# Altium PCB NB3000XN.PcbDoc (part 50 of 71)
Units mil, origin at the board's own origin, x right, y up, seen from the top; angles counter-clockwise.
Board outline 9527.56 x 6929.77 mil, 6 copper layers (Top Layer, GND+SHIELD, MidLayer1, MidLayer2, P2 - 3V3+5V0, Bottom Layer), stack 62.375 mil thick; 832 components, 1027 nets, 4655 pads, 4981 vias.
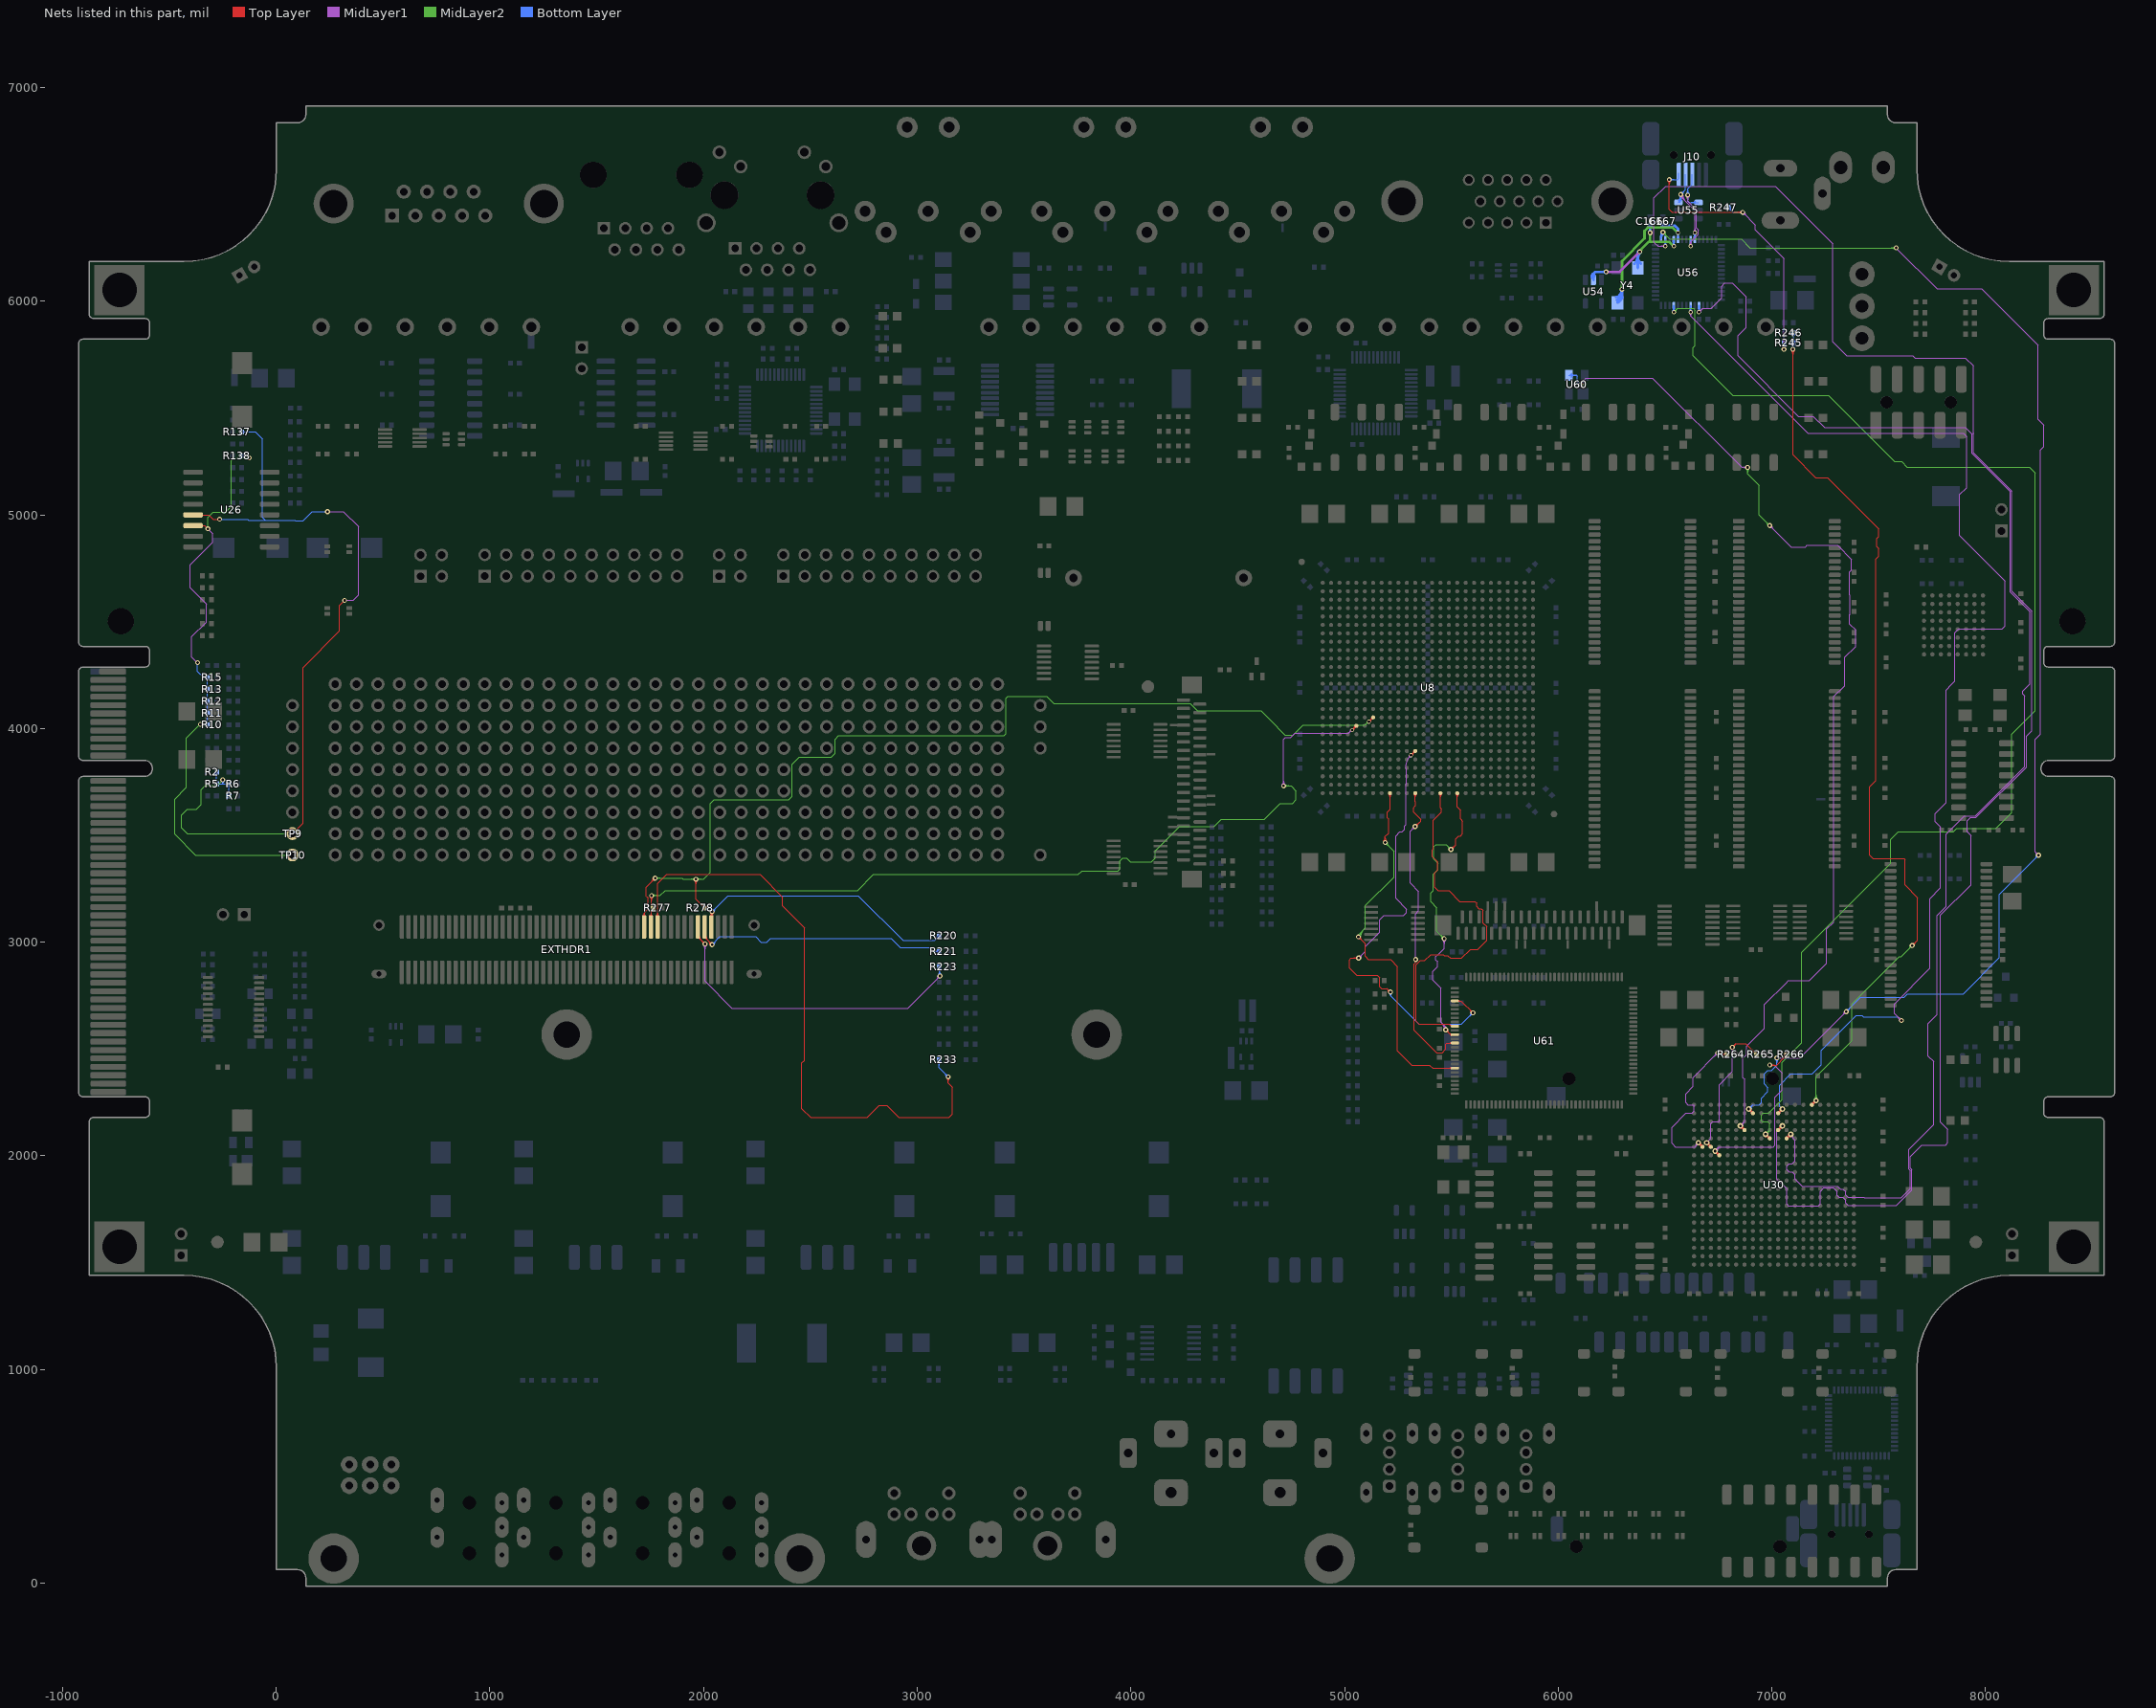
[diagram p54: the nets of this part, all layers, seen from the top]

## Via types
v1: diameter 23, hole 11.81, Top Layer to Bottom Layer, 3672 vias
v2: diameter 26, hole 11.81, Top Layer to Bottom Layer, 461 vias
v3: diameter 19, hole 11.81, Top Layer to Bottom Layer, tented both sides, 396 vias
v4: diameter 23.62, hole 11.81, Top Layer to Bottom Layer, 288 vias
v5: diameter 20, hole 11.81, Top Layer to Bottom Layer, 91 vias
v6: diameter 23, hole 11.81, Top Layer to Bottom Layer, tented both sides, 50 vias
v7: diameter 31, hole 11.81, Top Layer to Bottom Layer, 15 vias
v8: diameter 27.56, hole 11.81, Top Layer to Bottom Layer, tented both sides, 4 vias
v9: diameter 29, hole 11.81, Top Layer to Bottom Layer, 3 vias
v10: diameter 21, hole 11.81, Top Layer to Bottom Layer, 1 vias

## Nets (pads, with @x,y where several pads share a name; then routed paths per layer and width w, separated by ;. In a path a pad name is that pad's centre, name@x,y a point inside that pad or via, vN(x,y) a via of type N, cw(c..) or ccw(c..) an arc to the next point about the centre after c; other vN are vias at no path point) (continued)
HOST_USB.PKTEND: U30.L5 U56.39 | length 6330.3
  Top Layer w8: v2@6970.63,2092.22 cw(c6970.63,2070.49) 6985.99,2085.86 cw(c7001.36,2101.22) v2@6979.63,2101.22 ; v2(6970.63,2101.22) U30.L5@6990.31,2081.54 ; U30.L5@6984.47,2081.54 ccw(c6970.37,2081.54) 6980.34,2091.51 ccw(c6990.31,2101.48) U30.L5@6990.31,2087.38
  MidLayer2 w4: v5(6541.1,5949.34) 6557.66,5965.9 6632.66,5965.9 6640.19,5958.37 6640.19,5792.37 6631.86,5784.04 6631.86,5744.69 6818.17,5558.37 7265.19,5558.37 7573.52,5250.04 7606.86,5250.04 7632.9,5224 8204.69,5224 8231.86,5196.83 8231.86,4082.75 8122.86,3973.75 8122.86,3607.71 8048.52,3533.37 7865.19,3533.37 7848.52,3516.71 7591.86,3516.71 7556.86,3481.71 7556.86,3369.08 7139.86,2952.08 7139.86,2530.06 7048.52,2438.73 7048.52,2263.71 6984.86,2200.04 6959.19,2200.04 6950.86,2191.71 6950.86,2161.71 6952.86,2159.71 6981.86,2159.71 6990.19,2151.37 6990.19,2120.78 v2(6970.63,2101.22) ; v5@6541.1,5957.34 ccw(c6541.1,5976.65) 6554.76,5963 ccw(c6568.42,5949.34) v5@6549.1,5949.34 ; v2@6970.63,2108.22 ccw(c6970.63,2125.12) 6982.58,2113.17 ccw(c6994.53,2101.22) v2@6977.63,2101.22 ; v2@6970.63,2112.22 ccw(c6970.63,2138.78) 6989.41,2120 ccw(c7008.18,2101.22) v2@6981.63,2101.22
  Bottom Layer w8: v5@6536.86,5953.58 ccw(c6526.62,5963.82) 6541.1,5963.82 ccw(c6555.59,5963.82) v5@6545.34,5953.58 ; v5(6541.1,5949.34) U56.39@6541.1,5980.67
HOST_USB.RD_N: U30.N2 U56.1 | length 7277.6
  Top Layer w8: v2@6891.89,2210.33 cw(c6891.89,2188.6) 6907.25,2203.97 cw(c6922.62,2219.33) v2@6900.89,2219.33 ; v2(6891.89,2219.33) U30.N2@6911.57,2199.65 ; U30.N2@6905.73,2199.65 ccw(c6891.63,2199.65) 6901.6,2209.62 ccw(c6911.57,2219.59) U30.N2@6911.57,2205.49
  MidLayer1 w4: v1(7023.52,2458.37) 7131.86,2458.37 v1(7348.52,2675.04) ; v1@7027.41,2454.49 cw(c7036.8,2445.1) 7036.8,2458.37 cw(c7036.8,2471.65) v1@7027.41,2462.26 ; v1@7030.24,2451.66 cw(c7046.46,2435.44) 7046.46,2458.37 cw(c7046.46,2481.31) v1@7030.24,2465.09 ; v1@7339.02,2675.04 cw(c7316.09,2675.04) 7332.31,2658.82 cw(c7348.52,2642.61) v1@7348.52,2665.54 ; v1@7343.02,2675.04 cw(c7329.75,2675.04) 7339.14,2665.65 cw(c7348.52,2656.26) v1@7348.52,2669.54 ; v1(7581.86,6250.04) 7773.52,6058.37 7981.63,6058.37 8245,5795 8245,5448.52 8273.52,5420 8273.52,5320 8256.86,5303.33 8256.86,3974.43 8231.52,3949.1 8231.52,3424.04 v1(8248.52,3407.04) ; v1@8239.02,3407.04 ccw(c8216.09,3407.04) 8232.31,3423.26 ccw(c8248.52,3439.48) v1@8248.52,3416.54 ; v1@8243.02,3407.04 ccw(c8229.75,3407.04) 8239.14,3416.43 ccw(c8248.52,3425.82) v1@8248.52,3412.54
  MidLayer2 w4: v1@6490.19,6313.87 cw(c6490.19,6290.94) 6506.41,6307.16 cw(c6522.63,6323.37) v1@6499.69,6323.37 ; v1@6490.19,6317.87 cw(c6490.19,6304.6) 6499.58,6313.99 cw(c6508.97,6323.37) v1@6495.69,6323.37 ; v1(6490.19,6323.37) 6521.86,6291.71 6856.86,6291.71 6898.52,6250.04 v1(7581.86,6250.04) ; v1@7575.14,6243.32 ccw(c7558.92,6227.11) 7558.92,6250.04 ccw(c7558.92,6272.98) v1@7575.14,6256.76 ; v1@7577.97,6246.15 ccw(c7568.58,6236.76) 7568.58,6250.04 ccw(c7568.58,6263.32) v1@7577.97,6253.93
  Bottom Layer w4: U56.1@6479.22,6303.09 ccw(c6472.39,6309.92) 6482.05,6309.92 ccw(c6491.7,6309.92) U56.1@6484.88,6303.09 ; U56.1@6482.05,6288.37 cw(c6516.09,6288.37) v1@6495.84,6315.74 ; U56.1@6482.05,6289.33 6482.05,6315.23 v1(6490.19,6323.37) ; U56.1@6482.05,6296.31 cw(c6510.22,6296.31) v1@6493.46,6318.95 ; U56.1@6482.05,6304.24 cw(c6504.35,6304.24) v1@6491.08,6322.17 ; 6482.05,6312.18 cw(c6498.47,6312.18) v1@6488.7,6325.38 ; v2(6891.89,2219.33) 6910.93,2238.37 6940.19,2238.37 6951.52,2249.71 6951.52,2269.71 6981.86,2300.04 6981.86,2320.04 6965.19,2336.71 6965.19,2383.37 6981.86,2400.04 6998.52,2400.04 7023.52,2425.04 v1(7023.52,2458.37) ; v2@6891.89,2226.33 ccw(c6891.89,2243.23) 6903.84,2231.28 ccw(c6915.79,2219.33) v2@6898.89,2219.33 ; v2@6891.89,2230.33 ccw(c6891.89,2256.89) 6910.67,2238.11 ccw(c6929.45,2219.33) v2@6902.89,2219.33 ; v1@7016.81,2451.66 cw(c7000.59,2435.44) 7023.52,2435.44 cw(c7046.46,2435.44) v1@7030.24,2451.66 ; v1@7019.64,2454.49 cw(c7010.25,2445.1) 7023.52,2445.1 cw(c7036.8,2445.1) v1@7027.41,2454.49 ; v1(7348.52,2675.04) 7415.19,2741.71 7618.17,2741.71 7635.17,2758.71 7895.88,2758.71 8065.19,2928.02 8065.19,3223.71 v1(8248.52,3407.04) ; v1@7348.52,2680.54 ccw(c7348.52,2693.82) 7357.91,2684.43 ccw(c7367.3,2675.04) v1@7354.02,2675.04 ; v1@7348.52,2684.54 ccw(c7348.52,2707.48) 7364.74,2691.26 ccw(c7380.96,2675.04) v1@7358.02,2675.04 ; v1@8239.02,3407.04 cw(c8216.09,3407.04) 8232.31,3390.82 cw(c8248.52,3374.61) v1@8248.52,3397.54 ; v1@8243.02,3407.04 cw(c8229.75,3407.04) 8239.14,3397.65 cw(c8248.52,3388.26) v1@8248.52,3401.54
HOST_USB.READY: U30.J5 U56.33 | length 6901
  Top Layer w8: U30.J5@7069.06,2081.54 v2(7088.74,2101.22) ; U30.J5@7069.06,2087.38 ccw(c7069.06,2101.48) 7079.03,2091.51 ccw(c7089,2081.54) U30.J5@7074.9,2081.54 ; v2@7079.74,2101.22 cw(c7058.01,2101.22) 7073.38,2085.86 cw(c7088.74,2070.49) v2@7088.74,2092.22
  MidLayer1 w4: v5(6659.21,5949.34) 6676.58,5966.71 6715.86,5966.71 6765.19,6016.04 6765.19,6070 6780.19,6085 6815,6085 6880,6020 6880,5877.69 6841,5838.69 6841,5744.49 7125.14,5460.35 7194.18,5460.35 7246.15,5408.37 7905.23,5408.37 7934.28,5379.32 7936,5377.6 7936,5287.56 8115.19,5108.37 8115.19,4640 8208.52,4546.67 8208.52,4208.73 8175,4175.2 8175,4162.13 8183.19,4153.94 8183.19,3822.13 8150.03,3788.97 7952.43,3591.37 7901.17,3591.37 7815.19,3505.39 7815.19,3166.71 7773.52,3125.04 7773.52,2661.08 7731.52,2619.08 7731.52,2467.04 7756.86,2441.71 7756.86,2145.71 7640.52,2029.37 7640.52,1939.22 7647.5,1932.25 7647.5,1846 7605,1803.5 7535,1803.5 7432.63,1803.5 7430,1806.13 7356.96,1806.13 7345.33,1817.76 7345.33,1832.13 7332.83,1844.63 7320.6,1844.63 7315.19,1850.04 7306.86,1858.37 7141.19,1858.37 7108.36,1891.21 7108.36,1911.62 7095.24,1924.74 7080.87,1924.74 7069.74,1935.87 7069.74,1951.61 7080.87,1962.74 7095.24,1962.74 7108.36,1975.86 7108.36,2072.27 7099.02,2081.6 7098.92,2081.6 7098.92,2091.04 v2(7088.74,2101.22) ; v5@6659.21,5957.34 ccw(c6659.21,5976.66) 6672.87,5963 ccw(c6686.52,5949.34) v5@6667.21,5949.34 ; v2@7088.44,2094.23 cw(c7087.98,2083.29) 7098.92,2083.29 ; v2@7088.61,2098.22 cw(c7088.15,2087.47) 7098.92,2087.47 ; v2@7088.78,2102.22 cw(c7088.33,2091.64) 7098.92,2091.64
  Bottom Layer w8: v5@6654.97,5953.58 ccw(c6644.73,5963.82) 6659.21,5963.82 ccw(c6673.7,5963.82) v5@6663.45,5953.58 ; v5(6659.21,5949.34) U56.33@6659.21,5980.67
HOST_USB.RESET_N: U30.P4 U60.3 | length 5349.1
  Top Layer w8: v2@6852.52,2131.59 cw(c6852.52,2109.86) 6867.88,2125.23 cw(c6883.25,2140.59) v2@6861.52,2140.59 ; v2(6852.52,2140.59) U30.P4@6872.2,2120.91 ; U30.P4@6866.36,2120.91 ccw(c6852.26,2120.91) 6862.23,2130.88 ccw(c6872.2,2140.85) U30.P4@6872.2,2126.75
  MidLayer1 w4: v1@6104.86,5620.21 ccw(c6104.86,5633.49) 6114.25,5624.1 ccw(c6123.64,5614.71) v1@6110.36,5614.71 ; 6104.86,5624.21 ccw(c6104.86,5647.14) 6121.07,5630.93 ccw(c6137.29,5614.71) v1@6114.36,5614.71 ; v1(6105,5610) 6105,5614.56 6104.86,5614.71 6130.15,5640 6441.29,5640 6858.92,5222.37 v1(6886.86,5222.37) ; v2(6852.52,2140.59) 6852.52,2141.71 6872.86,2162.04 6872.86,2358.37 6865.19,2366.04 6865.19,2457.37 6881.86,2474.04 6881.86,2514.34 6965.19,2597.67 6965.19,2708.37 7069.5,2812.68 7076.82,2820 7176.21,2820 7256.86,2900.65 7256.86,3061.35 7290.19,3094.69 7290.19,4149.69 7340.86,4200.36 7340.86,4333.48 7391.86,4384.48 7391.86,4461.83 7364.52,4489.16 7364.52,4533.37 7365.19,4534.04 7365.19,4625.04 7364.52,4625.71 7364.52,4732.71 7373.52,4741.71 7373.52,4791.71 7306.86,4858.37 7165.19,4858.37 7156.86,4850.04 7090.19,4850.04 7077.48,4862.75 v1(6990.19,4950.04) ; v2@6852.52,2147.59 ccw(c6852.52,2161.8) 6862.57,2151.75 ; v2@6852.52,2151.59 ccw(c6852.52,2175.46) 6869.4,2158.58 ; v2@6859.52,2140.59 cw(c6879.11,2140.59) 6865.26,2154.44 ; v2@6863.52,2140.59 cw(c6892.76,2140.59) 6872.08,2161.27 ; v1@6880.14,5215.66 ccw(c6863.92,5199.44) 6863.92,5222.37 ccw(c6863.92,5245.31) v1@6880.14,5229.09 ; v1@6882.97,5218.49 ccw(c6873.58,5209.1) 6873.58,5222.37 ccw(c6873.58,5235.65) v1@6882.97,5226.26 ; v1@6990.19,4940.54 cw(c6990.19,4917.61) 7006.41,4933.82 cw(c7022.63,4950.04) v1@6999.69,4950.04 ; v1@6990.19,4944.54 cw(c6990.19,4931.26) 6999.58,4940.65 cw(c7008.97,4950.04) v1@6995.69,4950.04
  MidLayer2 w4: v1@6880.14,5215.66 cw(c6863.92,5199.44) 6886.86,5199.44 cw(c6909.79,5199.44) v1@6893.57,5215.66 ; v1@6882.97,5218.49 cw(c6873.58,5209.1) 6886.86,5209.1 cw(c6900.14,5209.1) v1@6890.75,5218.49 ; v1(6886.86,5222.37) 6886.86,5191.71 6940.19,5138.37 6940.19,5000.04 v1(6990.19,4950.04) ; v1@6980.69,4950.04 ccw(c6957.76,4950.04) 6973.97,4966.26 ccw(c6990.19,4982.48) v1@6990.19,4959.54 ; v1@6984.69,4950.04 ccw(c6971.41,4950.04) 6980.8,4959.43 ccw(c6990.19,4968.82) v1@6990.19,4955.54
  Bottom Layer w4: U60.3@6049.65,5653.31 6086.69,5653.31 ; U60.3@6055.19,5647.94 cw(c6067.83,5635.73) 6067.83,5653.31 cw(c6067.83,5670.89) U60.3@6055.19,5658.67 ; U60.3@6058.07,5645.17 cw(c6077.26,5626.62) 6077.26,5653.31 cw(c6077.26,5680) U60.3@6058.07,5661.45 ; U60.3@6060.95,5642.39 cw(c6086.69,5617.51) 6086.69,5653.31 ; U60.3@6060.95,5664.23 ccw(c6086.69,5689.11) 6086.69,5653.31 ; v1(6105,5610) 6090,5625 6090,5650 6086.69,5653.31
HOST_USB.SLOE: U30.K2 U56.35 | length 5896.7
  Top Layer w8: U30.K2@7029.69,2199.65 v2(7049.37,2219.33) ; U30.K2@7029.69,2205.49 ccw(c7029.69,2219.59) 7039.66,2209.62 ccw(c7049.63,2199.65) U30.K2@7035.53,2199.65 ; v2@7040.37,2219.33 cw(c7018.64,2219.33) 7034.01,2203.97 cw(c7049.37,2188.6) v2@7049.37,2210.33
  MidLayer1 w4: v5@6614.57,5943.32 cw(c6604.41,5931.7) 6619.84,5931.7 ; v5(6619.84,5949.34) 6619.84,5931.7 ; v5@6625.11,5943.32 ccw(c6635.28,5931.7) 6619.84,5931.7 ; v1@7597.36,2633.37 ccw(c7574.42,2633.37) 7590.64,2649.59 ccw(c7606.86,2665.81) v1@7606.86,2642.87 ; v1@7601.36,2633.37 ccw(c7588.08,2633.37) 7597.47,2642.76 ccw(c7606.86,2652.15) v1@7606.86,2638.87 ; v1(7606.86,2633.37) 7573.19,2667.04 7573.19,2710.41 7740.52,2877.75 7740.52,3204.37 7790.19,3254.04 7790.19,3540 7765.19,3565 7765.19,3603.04 7815.19,3653.04 7815.19,4180.71 7842.89,4208.41 7856.52,4222.04 7856.52,4449.71 7865.19,4458.37 7873.52,4466.71 8077.23,4466.71 8090.52,4480 8090.52,4691.37 8065.19,4716.71 7879.5,4902.4 7879.5,5094.72 7912,5127.23 7912,5367.66 7896.29,5383.37 7168.17,5383.37 6619.84,5931.7
  Bottom Layer w4: v2(7049.37,2219.33) 7036.86,2231.84 7036.86,2331.04 7089.19,2383.37 7189.19,2383.37 7231.86,2426.04 7231.86,2494.37 7394.19,2656.71 7422.21,2656.71 7428.88,2650.04 ; 7428.92,2650 7428.88,2650.04 ; v1@7597.36,2633.37 ccw(c7574.42,2633.37) 7590.64,2649.59 ccw(c7606.86,2665.81) v1@7606.86,2642.87 ; v1@7601.36,2633.37 ccw(c7588.08,2633.37) 7597.47,2642.76 ccw(c7606.86,2652.15) v1@7606.86,2638.87 ; v1(7606.86,2633.37) 7590.19,2650.04 7428.88,2650.04
  Bottom Layer w8: v5@6615.6,5953.58 ccw(c6605.36,5963.82) 6619.84,5963.82 ccw(c6634.33,5963.82) v5@6624.09,5953.58 ; v5(6619.84,5949.34) U56.35@6619.84,5980.67
HOST_USB.VBUS: R245.1 R246.1 U30.F1 | length 4741.7
  Top Layer w4: v1@7091.81,5768.66 cw(c7075.59,5752.44) 7098.52,5752.44 cw(c7121.46,5752.44) v1@7105.24,5768.66 ; v1@7094.64,5771.49 cw(c7085.25,5762.1) 7098.52,5762.1 cw(c7111.8,5762.1) v1@7102.41,5771.49 ; v1(7098.52,5775.37) 7098.52,5281.48 7204.96,5175.04 7259.84,5175.04 7500.19,4934.69 7500.19,4898.01 7491.19,4889 7491.19,4851 7500.19,4841.99 7500.19,4807.73 7486.19,4793.73 7486.19,3756.04 7456.86,3726.71 7456.86,3408.37 7473.52,3391.71 7618.52,3391.71 7623.52,3386.71 7623.52,3267.39 7681.86,3209.06 7681.86,3009.71 v1(7656.86,2984.71) ; v1@7656.86,2990.21 ccw(c7656.86,3003.49) 7666.25,2994.1 ccw(c7675.64,2984.71) v1@7662.36,2984.71 ; v1@7656.86,2994.21 ccw(c7656.86,3017.14) 7673.07,3000.93 ccw(c7689.29,2984.71) v1@7666.36,2984.71
  Top Layer w8: U30.F1@7187.17,2239.02 v2(7206.85,2258.7) ; U30.F1@7187.17,2244.86 ccw(c7187.17,2258.96) 7197.14,2248.99 ccw(c7207.11,2239.02) U30.F1@7193.01,2239.02 ; v2@7197.85,2258.7 cw(c7176.12,2258.7) 7191.49,2243.34 cw(c7206.85,2227.97) v2@7206.85,2249.7
  MidLayer2 w4: v2@7199.07,2266.48 ccw(c7180.29,2285.26) 7206.85,2285.26 ccw(c7233.41,2285.26) v2@7214.63,2266.48 ; v2@7201.9,2263.65 ccw(c7189.95,2275.6) 7206.85,2275.6 ccw(c7223.75,2275.6) v2@7211.8,2263.65 ; v2(7206.85,2258.7) 7206.85,2370.35 7374.19,2537.69 7374.19,2710.37 7597.19,2933.37 7605.52,2933.37 v1(7656.86,2984.71) ; v1@7647.36,2984.71 cw(c7624.42,2984.71) 7640.64,2968.49 cw(c7656.86,2952.27) v1@7656.86,2975.21 ; v1@7651.36,2984.71 cw(c7638.08,2984.71) 7647.47,2975.32 cw(c7656.86,2965.93) v1@7656.86,2979.21
  Bottom Layer w4: v1@7091.81,5782.09 ccw(c7069.17,5804.72) R245.1@7101.18,5804.72 ; R245.1@7094.59,5797.92 cw(c7078.68,5782.01) 7101.18,5782.01 cw(c7123.68,5782.01) R245.1@7107.77,5797.92 ; R245.1@7094.59,5812.08 ccw(c7078.68,5827.99) 7101.18,5827.99 ccw(c7123.68,5827.99) R245.1@7107.77,5812.08 ; R246.1@7094.59,5845.42 cw(c7078.68,5829.51) 7101.18,5829.51 cw(c7123.68,5829.51) R246.1@7107.77,5845.42 ; v1@7094.64,5779.26 ccw(c7078.83,5795.07) R245.1@7101.18,5795.07 ; R245.1@7097.42,5800.75 cw(c7088.34,5791.67) 7101.18,5791.67 cw(c7114.02,5791.67) R245.1@7104.94,5800.75 ; R245.1@7097.42,5809.25 ccw(c7088.34,5818.33) 7101.18,5818.33 ccw(c7114.02,5818.33) R245.1@7104.94,5809.25 ; R246.1@7097.42,5848.25 cw(c7088.34,5839.17) 7101.18,5839.17 cw(c7114.02,5839.17) R246.1@7104.94,5848.25 ; v1(7098.52,5775.37) 7101.18,5778.03 R245.1@7101.18,5805 R246.1@7101.18,5852.5 ; 7101.18,5791.9 ccw(c7115.04,5791.9) v1@7105.24,5782.09
HOST_USB.WR_N: U30.K4 U56.2 | length 8106.8
  Top Layer w8: U30.K4@7029.69,2120.91 v2(7049.37,2140.59) ; U30.K4@7029.69,2126.75 ccw(c7029.69,2140.85) 7039.66,2130.88 ccw(c7049.63,2120.91) U30.K4@7035.53,2120.91 ; v2@7040.37,2140.59 cw(c7018.64,2140.59) 7034.01,2125.23 cw(c7049.37,2109.86) v2@7049.37,2131.59
  MidLayer1 w4: v5@6496.08,6252.34 ccw(c6482.42,6238.69) 6482.42,6258 ccw(c6482.42,6277.31) v5@6496.08,6263.66 ; v5(6501.73,6258) 6467.23,6258 6448.52,6276.71 6448.52,6483.52 6504,6539 7015.63,6539 7285,6269.63 7285,5810 7350,5745 7660,5745 7670,5735 7905,5735 7942.81,5697.19 7942.81,5381.8 7944,5380.61 ; v2@7038.37,2140.59 cw(c7011.81,2140.59) 7030.59,2121.81 cw(c7049.37,2103.03) v2@7049.37,2129.59 ; v2@7042.37,2140.59 cw(c7025.47,2140.59) 7037.42,2128.64 cw(c7049.37,2116.69) v2@7049.37,2133.59 ; v2(7049.37,2140.59) 7023.82,2115.04 7023.82,1891.41 7069.52,1845.71 7069.52,1775.04 7077.86,1766.71 7218.19,1766.71 7226.52,1775.04 7226.52,1833.37 7243.19,1850.04 7288.52,1850.04 7305.19,1833.37 7305.19,1816.04 7315.19,1806.04 7332.05,1806.04 7345.33,1792.76 7345.33,1778.39 7356.46,1767.26 7582.51,1767.26 7655.5,1840.25 7655.5,1935.56 7648.52,1942.54 7648.52,1996.71 7701.86,2050.04 7812.86,2050.04 7823.52,2060.71 7823.52,2125.04 7790.19,2158.37 7790.19,3126.37 7931.86,3268.04 7931.86,3500.04 7915.19,3516.71 7915.19,3569.37 7929.19,3583.37 7955.75,3583.37 8191.19,3818.82 8191.19,3965.33 8216.52,3990.67 8216.52,4549.98 8123.19,4643.31 8123.19,5111.69 7944,5290.88 7944,5380.61 ; 7944,5380.92 7944,5380.61
  Bottom Layer w8: v5@6497.49,6262.24 ccw(c6487.25,6272.49) 6501.73,6272.49 ccw(c6516.22,6272.49) v5@6505.97,6262.24 ; v5(6501.73,6258) U56.2@6501.73,6289.33
HOST_USB.XTALIN: C167.1 U56.5 Y4.3 | length 905.6
  MidLayer2 w12: v1@6294.64,6059.93 ccw(c6285.25,6069.32) 6298.52,6069.32 ccw(c6311.8,6069.32) v1@6302.41,6059.93 ; v1(6298.52,6056.04) 6298.52,6188.52 6404.39,6294.39 6404.39,6329.39 6420,6345 6536.45,6345 v5(6560.79,6320.66)
  Bottom Layer w8: v5@6556.54,6316.42 cw(c6546.3,6306.18) 6560.79,6306.18 cw(c6575.27,6306.18) v5@6565.03,6316.42 ; U56.5@6560.79,6289.33 v5(6560.79,6320.66)
  Bottom Layer w12: Y4.3@6270.85,6017.95 ccw(c6258.47,6056.04) v1(6298.52,6056.04) 6298.52,6014.52 Y4.3@6277.5,5993.5 ; Y4.3@6274.56,6006.53 ccw(c6263.84,6039.52) 6298.52,6039.52 ; Y4.3@6278.27,5995.12 ccw(c6269.21,6023) Y4.3@6298.52,6023 ; v1@6294.64,6052.15 cw(c6285.25,6042.76) 6298.52,6042.76 cw(c6311.8,6042.76) v1@6302.41,6052.15 ; C167.1@6490,6354.33 6545.67,6354.33 6560.79,6339.21 v5(6560.79,6320.66) ; C167.1@6494.11,6350.22 cw(c6504.03,6340.3) 6504.03,6354.33 cw(c6504.03,6368.36) C167.1@6494.11,6358.44
HOST_USB.XTALOUT: C166.1 U54.2 U56.4 Y4.1 | length 1026.5
  MidLayer1 w12: v1(6224.15,6137.69) 6287.84,6137.69 v1(6381.86,6231.71) ; v1@6228.04,6133.8 cw(c6237.43,6124.41) 6237.43,6137.69 cw(c6237.43,6150.97) v1@6228.04,6141.58 ; v1@6376.36,6231.71 cw(c6363.08,6231.71) 6372.47,6222.32 cw(c6381.86,6212.93) v1@6381.86,6226.21
  MidLayer2 w12: v1(6381.86,6231.71) 6381.86,6236.86 6423,6278 6430,6278 ; v1@6387.36,6231.71 cw(c6413.07,6231.71) 6394.89,6249.89 ; v1@6426.3,6317.15 cw(c6416.91,6307.76) 6430.19,6307.76 cw(c6443.47,6307.76) v1@6434.08,6317.15 ; v1(6430.19,6321.04) 6430.19,6278.19 6430,6278 ; v5(6541.1,6258) 6521.1,6278 6430,6278
  Bottom Layer w8: v5@6536.86,6262.24 ccw(c6526.62,6272.49) 6541.1,6272.49 ccw(c6555.59,6272.49) v5@6545.35,6262.24 ; v5(6541.1,6258) U56.4@6541.1,6289.33
  Bottom Layer w12: U54.2@6159.66,6110.77 cw(c6171,6117.41) 6161.71,6126.71 ; U54.2@6160.89,6118.01 ccw(c6150.97,6127.93) 6165,6127.93 ccw(c6179.03,6127.93) U54.2@6169.11,6118.01 ; U54.2@6165,6100.12 6165,6130 6172.69,6137.69 ; U54.2@6170.01,6116.84 cw(c6184.85,6125.53) 6172.69,6137.69 ; v1@6220.26,6133.8 ccw(c6210.87,6124.41) 6210.87,6137.69 ccw(c6210.87,6150.97) v1@6220.26,6141.58 ; v1(6224.15,6137.69) 6172.69,6137.69 ; Y4.1@6357.3,6175.7 ccw(c6320.59,6212.41) 6372.5,6212.41 ccw(c6424.41,6212.41) Y4.1@6387.7,6175.7 ; Y4.1@6372.5,6156.5 6372.5,6222.35 v1(6381.86,6231.71) ; 6372.5,6195.84 cw(c6417.73,6195.84) v1@6385.75,6227.82 ; 6372.5,6224.81 cw(c6388.76,6224.81) v1@6377.26,6236.3 ; C166.1@6425.89,6350.22 cw(c6415.97,6340.3) 6430,6340.3 cw(c6444.03,6340.3) C166.1@6434.11,6350.22 ; v1@6426.3,6324.93 ccw(c6417.37,6333.86) 6430,6333.86 ; 6430,6334.78 ccw(c6443.93,6334.78) v1@6434.08,6324.93 ; C166.1@6430,6354.33 6430,6321.23 v1(6430.19,6321.04)
HOST_VS0: R264.1 U30.W6 | length 992.6
  Top Layer w4: v1(6746.52,2481.37) 6765,2481.37 ; v1@6754.25,2475.85 cw(c6765,2468.16) 6765,2481.37 ; v1@6754.25,2486.9 ccw(c6765,2494.59) 6765,2481.37 ; R264.1@6781.07,2469.82 ccw(c6771.38,2463.33) 6771.38,2475 ; R264.1@6781.07,2480.18 cw(c6771.38,2486.67) 6771.38,2475 ; R264.1@6788.82,2475 6771.38,2475 ; 6765,2481.37 6771.38,2475
  Top Layer w8: v2@6655.67,2052.85 cw(c6655.67,2031.12) 6671.03,2046.49 cw(c6686.4,2061.85) v2@6664.67,2061.85 ; v2(6655.67,2061.85) U30.W6@6675.35,2042.17 ; U30.W6@6669.51,2042.17 ccw(c6655.41,2042.17) 6665.38,2052.14 ccw(c6675.35,2062.11) U30.W6@6675.35,2048.01
  MidLayer1 w4: 6642.52,2044.04 ccw(c6633.4,2053.17) v2@6645.42,2057.85 ; 6644.85,2046.37 cw(c6655.67,2035.55) v2@6655.67,2050.85 ; 6646.85,2048.37 ccw(c6639.63,2055.6) v2@6649.15,2059.31 ; v2(6655.67,2061.85) 6656.86,2061.85 6656.86,2058.37 6640.19,2041.71 6548.52,2041.71 6531.86,2058.37 6531.86,2133.37 6598.52,2200.04 6627.19,2200.04 6635.52,2208.37 6635.52,2236.71 6633.52,2238.71 6606.86,2238.71 6596.86,2248.71 6596.86,2290.04 6631.86,2325.04 6631.86,2366.71 v1(6746.52,2481.37) ; v1@6737.02,2481.37 cw(c6714.09,2481.37) 6730.31,2465.16 cw(c6746.52,2448.94) v1@6746.52,2471.87 ; v1@6741.02,2481.37 cw(c6727.75,2481.37) 6737.14,2471.99 cw(c6746.52,2462.6) v1@6746.52,2475.87
HOST_VS1: R265.1 U30.V6 | length 907.6
  Top Layer w4: v1(6815.19,2508.37) 6831.86,2525.04 6878.78,2525.04 R265.1@6928.82,2475 ; v1@6815.19,2513.87 ccw(c6815.19,2527.15) 6824.58,2517.76 ccw(c6833.97,2508.37) v1@6820.69,2508.37 ; v1@6815.19,2517.87 ccw(c6815.19,2540.81) 6831.41,2524.59 ccw(c6847.63,2508.37) v1@6824.69,2508.37 ; 6912.07,2491.75 ccw(c6928.82,2508.5) R265.1@6928.82,2484.81 ; 6913.26,2490.56 cw(c6898.19,2475.49) R265.1@6919.5,2475.49 ; R265.1@6918.9,2484.92 ccw(c6928.82,2494.84) R265.1@6928.82,2480.81 ; R265.1@6920.09,2483.73 cw(c6911.85,2475.49) R265.1@6923.5,2475.49
  Top Layer w8: v2@6695.04,2052.85 cw(c6695.04,2031.12) 6710.4,2046.49 cw(c6725.77,2061.85) v2@6704.04,2061.85 ; v2(6695.04,2061.85) U30.V6@6714.72,2042.17 ; U30.V6@6708.88,2042.17 ccw(c6694.78,2042.17) 6704.75,2052.14 ccw(c6714.72,2062.11) U30.V6@6714.72,2048.01
  MidLayer1 w4: v2(6695.04,2061.85) 6715.19,2082 6715.19,2152.04 6723.52,2160.37 6751.86,2160.37 6753.52,2162.04 6753.52,2333.37 6815.19,2395.04 v1(6815.19,2508.37) ; v1@6808.47,2501.66 cw(c6792.26,2485.44) 6815.19,2485.44 cw(c6838.13,2485.44) v1@6821.91,2501.66 ; v1@6811.3,2504.49 cw(c6801.91,2495.1) 6815.19,2495.1 cw(c6828.47,2495.1) v1@6819.08,2504.49
HOST_VS2: R266.1 U30.U7 | length 1108.6
  Top Layer w4: v1(6990.19,2425.04) 7023.52,2425.04 7060.19,2461.71 7068.82,2461.71 ; v1@6994.08,2421.15 cw(c7003.47,2411.76) 7003.47,2425.04 cw(c7003.47,2438.32) v1@6994.08,2428.93 ; v1@6996.91,2418.32 cw(c7013.13,2402.11) 7013.13,2425.04 cw(c7013.13,2447.98) v1@6996.91,2431.76 ; 7049.96,2451.48 ccw(c7026.93,2474.51) R266.1@7059.5,2474.51 ; 7056.79,2458.31 ccw(c7040.59,2474.51) R266.1@7063.5,2474.51 ; 7060.03,2461.55 cw(c7068.82,2452.76) R266.1@7068.82,2465.19 ; R266.1@7068.82,2475 7068.82,2461.71 ; 7068.82,2461.71 cw(c7072.95,2461.71) 7071.68,2465.64 ccw(c7072.95,2461.71) 7068.82,2461.71 ; 7068.82,2461.71 ccw(c7064.69,2461.71) 7065.96,2465.64 cw(c7064.69,2461.71) 7068.82,2461.71
  Top Layer w8: v2@6734.41,2013.48 cw(c6734.41,1991.75) 6749.77,2007.12 cw(c6765.14,2022.48) v2@6743.41,2022.48 ; v2(6734.41,2022.48) U30.U7@6754.09,2002.8 ; U30.U7@6748.25,2002.8 ccw(c6734.15,2002.8) 6744.12,2012.77 ccw(c6754.09,2022.74) U30.U7@6754.09,2008.64
  MidLayer1 w4: v2(6734.41,2022.48) 6753.64,2041.71 7006.9,2041.71 7015.19,2050 7015.19,2275.04 7048.52,2308.37 7048.52,2388.73 7012.21,2425.04 v1(6990.19,2425.04) ; v2@6734.41,2029.48 ccw(c6734.41,2046.38) 6746.36,2034.43 ccw(c6758.31,2022.48) v2@6741.41,2022.48 ; v2@6734.41,2033.48 ccw(c6734.41,2060.04) 6753.19,2041.26 ccw(c6771.96,2022.48) v2@6745.41,2022.48
HOSTUSB#.DMINUS: J10.2 U55.6 U56.9 | length 744.1
  MidLayer1 w4: v1@6571.02,6500.04 ccw(c6588.84,6500.04) 6576.24,6487.44 ; v1(6573.52,6500.04) 6573.52,6490.16 6639.53,6424.16 v5(6639.53,6320.66) ; v1@6575.02,6500.04 ccw(c6602.49,6500.04) 6583.07,6480.62 ; v1@6579.02,6500.04 ccw(c6616.15,6500.04) 6589.9,6473.79 ; v1@6583.02,6500.04 ccw(c6629.81,6500.04) 6596.73,6466.96 ; v5@6633.87,6326.32 ccw(c6620.21,6339.98) 6639.53,6339.98 ccw(c6658.84,6339.97) v5@6645.18,6326.32
  Bottom Layer w4: U55.6@6561.32,6471.62 ccw(c6538.71,6500) v1@6575,6500 ; U55.6@6562.76,6462.4 U55.6@6575,6474.65 ; U55.6@6563.81,6468.49 ccw(c6545.32,6491.7) v1@6575,6491.7 ; U55.6@6566.31,6465.36 ccw(c6551.94,6483.4) 6575,6483.4 ; v1@6567.01,6493.13 cw(c6549.54,6474.6) U55.6@6575,6474.6 ; U55.6@6568.8,6462.23 ccw(c6558.55,6475.1) U55.6@6575,6475.1 ; v1@6569.75,6496.04 cw(c6558.28,6483.87) 6575,6483.87 ; v1(6573.52,6500.04) 6596.5,6523.01 J10.2@6596.5,6594 ; v1@6573.52,6505.54 ccw(c6573.52,6518.82) 6582.91,6509.43 ccw(c6592.3,6500.04) v1@6579.02,6500.04 ; v1@6573.52,6509.54 ccw(c6573.52,6532.48) 6589.74,6516.26 ccw(c6605.96,6500.04) v1@6583.02,6500.04 ; U55.6@6575,6475.54 ccw(c6581.8,6475.54) U55.6@6576.99,6470.73 ; 6575,6480.67 cw(c6592.9,6480.67) v1@6580.24,6493.32 ; v1@6575,6500 U55.6@6575,6474.65
  Bottom Layer w8: v5@6635.28,6316.42 cw(c6625.04,6306.18) 6639.53,6306.18 cw(c6654.01,6306.18) v5@6643.77,6316.42 ; U56.9@6639.53,6289.33 v5(6639.53,6320.66)
HOSTUSB#.DPLUS: J10.3 U55.1 U56.8 | length 768.6
  MidLayer1 w4: v1@6599.47,6490.32 cw(c6583.26,6474.11) 6606.19,6474.11 cw(c6629.13,6474.11) v1@6612.91,6490.32 ; v1@6602.3,6493.15 cw(c6592.91,6483.76) 6606.19,6483.76 cw(c6619.47,6483.76) v1@6610.08,6493.15 ; v1(6606.19,6497.04) 6606.19,6468.81 6626.16,6448.84 6647.53,6427.47 6647.53,6343 6655.53,6335 6655.53,6314.03 6619.84,6278.35 v5(6619.84,6258) ; v5@6614.19,6263.66 ccw(c6600.53,6277.31) 6619.84,6277.31 ccw(c6639.16,6277.31) v5@6625.5,6263.66
  Bottom Layer w4: v1@6599.47,6490.32 cw(c6582.93,6473.78) 6606.33,6473.78 ; v1@6599.47,6503.76 ccw(c6583.26,6519.98) 6606.19,6519.98 ; v1@6602.3,6493.15 cw(c6592.58,6483.43) 6606.33,6483.43 ; v1@6602.3,6500.93 ccw(c6592.91,6510.32) 6606.19,6510.32 ccw(c6619.47,6510.32) v1@6610.08,6500.93 ; v1(6606.19,6497.04) 6606.33,6497.04 6606.33,6468.67 6612.6,6462.4 U55.1@6657.24,6462.4 ; 6606.33,6474.43 cw(c6628.8,6474.43) v1@6612.91,6490.32 ; 6606.33,6484.09 cw(c6619.14,6484.09) v1@6610.08,6493.15 ; v1@6612.91,6503.76 cw(c6629.13,6519.98) 6606.19,6519.98 ; J10.3@6627.99,6594 6627.99,6547.99 6606.19,6526.19 6606.19,6519.98 ; U55.1@6643.01,6454.07 ccw(c6622.9,6433.96) 6622.9,6462.4 ccw(c6622.9,6490.84) U55.1@6643.01,6470.73 ; U55.1@6645.84,6456.9 ccw(c6632.56,6443.62) 6632.56,6462.4 ccw(c6632.56,6481.18) U55.1@6645.84,6467.9
  Bottom Layer w8: v5@6615.6,6262.24 ccw(c6605.36,6272.49) 6619.84,6272.49 ccw(c6634.33,6272.49) v5@6624.09,6262.24 ; v5(6619.84,6258) U56.8@6619.84,6289.33
HOSTUSB#.VBUS: J10.1 R245.2 R247.1 | length 1801.4
  Top Layer w4: v1@6513.28,6563.28 cw(c6497.06,6547.06) 6520,6547.06 cw(c6542.93,6547.06) v1@6526.72,6563.28 ; v1@6516.11,6566.11 cw(c6506.72,6556.72) 6520,6556.72 cw(c6533.28,6556.72) v1@6523.89,6566.11 ; v1(6520,6570) 6520,6430 6533.29,6416.71 v1(6863.86,6416.71) ; v1@6857.14,6409.99 ccw(c6840.92,6393.77) 6840.92,6416.71 ccw(c6840.92,6439.64) v1@6857.14,6423.43 ; v1@6859.97,6412.82 ccw(c6850.58,6403.43) 6850.58,6416.71 ccw(c6850.58,6429.99) v1@6859.97,6420.6
  MidLayer1 w4: v1@6863.86,6407.21 cw(c6863.86,6384.27) 6880.07,6400.49 cw(c6896.29,6416.71) v1@6873.36,6416.71 ; v1@6863.86,6411.21 cw(c6863.86,6397.93) 6873.25,6407.32 cw(c6882.64,6416.71) v1@6869.36,6416.71 ; v1(6863.86,6416.71) 6923,6357.56 6923,6334.62 7056.86,6200.77 v1(7056.86,5775.04) ; v1@7050.14,5781.76 ccw(c7033.92,5797.98) 7056.86,5797.98 ccw(c7079.79,5797.98) v1@7063.57,5781.76 ; v1@7052.97,5778.93 ccw(c7043.58,5788.32) 7056.86,5788.32 ccw(c7070.14,5788.32) v1@7060.75,5778.93
  Bottom Layer w4: v1(6520,6570) 6560,6570 6565,6575 J10.1@6565,6600 ; v1@6523.89,6566.11 cw(c6533.28,6556.72) 6533.28,6570 cw(c6533.28,6583.28) v1@6523.89,6573.89 ; v1@6526.72,6563.28 cw(c6542.93,6547.06) 6542.93,6570 cw(c6542.93,6592.93) v1@6526.72,6576.72 ; R247.1@6795,6440 6818.29,6416.71 v1(6863.86,6416.71) ; R247.1@6796.18,6430.19 cw(c6796.18,6409.35) 6810.91,6424.09 ; R247.1@6796.18,6434.19 cw(c6796.18,6423.01) R247.1@6804.08,6430.92 ; R247.1@6801.5,6439.51 ccw(c6816,6439.51) R247.1@6805.75,6429.25 ; R247.1@6805.5,6439.51 ccw(c6829.66,6439.51) 6812.58,6422.42 ; v1@6857.14,6409.99 ccw(c6840.92,6393.77) 6840.92,6416.71 ccw(c6840.92,6439.64) v1@6857.14,6423.43 ; v1@6859.97,6412.82 ccw(c6850.58,6403.43) 6850.58,6416.71 ccw(c6850.58,6429.99) v1@6859.97,6420.6 ; R245.2@7055.54,5795.79 cw(c7053.75,5791.04) 7058.82,5791.04 ; v1(7056.86,5775.04) 7056.86,5789.08 7058.82,5791.04 ; R245.2@7058.82,5805 7058.82,5791.04 ; R245.2@7062.1,5795.79 ccw(c7063.89,5791.04) 7058.82,5791.04
I2C.SCL: EXTHDR1.25 R277.2 U8.V5 | length 4493.7
  Top Layer w4: EXTHDR1.25@1747.71,3122.62 ccw(c1725.64,3144.7) 1756.86,3144.7 ; v1@1750.14,3211.66 cw(c1733.92,3195.44) 1756.86,3195.44 cw(c1779.79,3195.44) v1@1763.57,3211.66 ; EXTHDR1.25@1750.54,3119.8 ccw(c1735.29,3135.04) 1756.86,3135.04 ; v1@1752.97,3214.49 cw(c1743.58,3205.1) 1756.86,3205.1 cw(c1770.14,3205.1) v1@1760.75,3214.49 ; EXTHDR1.25@1756.86,3075.04 v1(1756.86,3218.37) ; 1756.86,3127.86 ccw(c1764.26,3127.86) EXTHDR1.25@1759.03,3122.62 ; v3(5035.67,3993.15) U8.V5@5055.35,4012.83 ; v3@5043.17,3993.15 cw(c5061.28,3993.15) 5048.47,4005.95 ; v3@5043.17,3993.15 cw(c5061.28,3993.15) 5048.47,4005.95 ; U8.V5@5047.85,4012.83 cw(c5029.75,4012.83) 5042.55,4000.03 cw(c5055.35,3987.23) U8.V5@5055.35,4005.33 ; U8.V5@5048.01,4012.83 cw(c5030.29,4012.83) 5042.82,4000.3 cw(c5055.35,3987.77) U8.V5@5055.35,4005.49 ; 5048.47,4005.95 cw(c5035.67,4018.76) 5035.67,4000.65 ccw(c5035.67,4018.76) 5048.47,4005.95
  MidLayer1 w4: v1@4708.47,3738.09 ccw(c4692.26,3754.31) 4715.19,3754.31 ccw(c4738.13,3754.31) v1@4721.91,3738.09 ; v1@4711.3,3735.26 ccw(c4701.91,3744.65) 4715.19,3744.65 ccw(c4728.47,3744.65) v1@4719.08,3735.26 ; v1(4715.19,3731.37) 4715.19,3950.04 4723.52,3958.37 4749.04,3958.37 4768.31,3977.64 4860,3977.64 4870,3977.64 4918.62,3977.64 5012.16,3977.64 ccw(c5012.16,3991.69) 5022.09,3981.76 ; v3@5028.2,3993.8 cw(c5010.16,3995.38) 5021.8,3981.51 cw(c5033.44,3967.64) v3@5035.02,3985.68
  MidLayer2 w4: v1(1756.86,3218.37) 1797.06,3218.37 1820.39,3241.71 2720.54,3241.71 2795.54,3316.71 3753.88,3316.71 3771.17,3334 3939,3334 3948,3343 3948,3380 3961,3393 3980.56,3393 3998.52,3375.04 4096.52,3375.04 4115.19,3393.71 4115.19,3428.04 4228.86,3541.71 4390.19,3541.71 4423.52,3575.04 4624.52,3575.04 4699.52,3650.04 4756.52,3650.04 4773.52,3667.04 4773.52,3707.71 4749.86,3731.37 v1(4715.19,3731.37) ; v1@1760.75,3214.49 cw(c1770.14,3205.1) 1770.14,3218.37 cw(c1770.14,3231.65) v1@1760.75,3222.26 ; v1@1763.57,3211.66 cw(c1779.79,3195.44) 1779.79,3218.37 cw(c1779.79,3241.31) v1@1763.57,3225.09 ; v1@4719.08,3727.49 cw(c4728.47,3718.1) 4728.47,3731.37 cw(c4728.47,3744.65) v1@4719.08,3735.26 ; v1@4721.91,3724.66 cw(c4738.13,3708.44) 4738.13,3731.37 cw(c4738.13,3754.31) v1@4721.91,3738.09
I2C.SDA: EXTHDR1.27 R278.1 U8.U7 | length 5119.1
  Top Layer w4: EXTHDR1.27@1716.22,3122.62 ccw(c1702.56,3136.28) 1721.87,3136.28 ccw(c1741.19,3136.28) EXTHDR1.27@1727.53,3122.62 ; EXTHDR1.27@1721.87,3071.85 1721.87,3136.87 1741.1,3156.1 1741.1,3205.76 1735.41,3211.45 1731.86,3215 1731.86,3258.37 v1(1773.52,3300.04) ; v1@1764.02,3300.04 cw(c1741.09,3300.04) 1757.31,3283.82 cw(c1773.52,3267.61) v1@1773.52,3290.54 ; v1@1768.02,3300.04 cw(c1754.75,3300.04) 1764.13,3290.65 cw(c1773.52,3281.26) v1@1773.52,3294.54 ; v1@1957.62,3288.28 cw(c1941.4,3272.06) 1964.34,3272.06 cw(c1987.27,3272.06) v1@1971.06,3288.28 ; v1@1960.45,3291.11 cw(c1951.06,3281.72) 1964.34,3281.72 cw(c1977.62,3281.72) v1@1968.23,3291.11 ; v1(1964.34,3295) 1964.34,3202.39 R278.1@2006.7,3160.03 ; 1989.95,3176.78 ccw(c2006.7,3193.52) R278.1@2006.7,3169.84 ; 1991.14,3175.59 cw(c1976.07,3160.52) R278.1@1997.38,3160.52 ; R278.1@1996.78,3169.95 ccw(c2006.7,3179.87) R278.1@2006.7,3165.84 ; R278.1@1997.97,3168.76 cw(c1989.73,3160.52) R278.1@2001.38,3160.52 ; v3(5114.41,4032.52) U8.U7@5134.09,4052.2 ; U8.U7@5126.59,4052.2 cw(c5108.49,4052.2) 5121.29,4039.4 cw(c5134.09,4026.6) U8.U7@5134.09,4044.7 ; U8.U7@5126.75,4052.2 cw(c5109.03,4052.2) 5121.56,4039.67 cw(c5134.09,4027.14) U8.U7@5134.09,4044.86 ; 5127.21,4045.32 cw(c5114.41,4058.13) 5114.41,4040.02 ccw(c5114.41,4058.13) 5127.21,4045.32 ; 5127.21,4045.32 ccw(c5140.02,4032.52) 5121.91,4032.52 cw(c5140.02,4032.52) 5127.21,4045.32
  MidLayer2 w4: v1@1777.41,3296.15 cw(c1786.8,3286.76) 1786.8,3300.04 cw(c1786.8,3313.32) v1@1777.41,3303.93 ; v1@1780.24,3293.32 cw(c1796.46,3277.11) 1796.46,3300.04 ; v1@1780.24,3306.76 ccw(c1796.46,3322.98) 1796.46,3300.04 ; v1@1957.62,3288.28 ccw(c1941.4,3272.06) 1941.4,3295 ccw(c1941.4,3317.93) v1@1957.62,3301.72 ; v1@1960.45,3291.11 ccw(c1951.06,3281.72) 1951.06,3295 ccw(c1951.06,3308.28) v1@1960.45,3298.89 ; v1@1968.23,3291.11 cw(c1977.62,3281.72) 1977.62,3295 cw(c1977.62,3308.28) v1@1968.23,3298.89 ; v1@1971.06,3288.28 cw(c1987.27,3272.06) 1987.27,3295 cw(c1987.27,3317.93) v1@1971.06,3301.72 ; 5100.83,4021.13 cw(c5090.9,4031.06) 5090.9,4017.01 4997.36,4017.01 4870,4017.01 4860,4017.01 4807.16,4017.01 4760.19,3970.04 4721.67,3970.04 4648.64,4043.07 4608.33,4083.37 4312.21,4083.37 4278.88,4116.71 3640.19,4116.71 3606.86,4150.04 3423.52,4150.04 3415.19,4141.71 3415.19,3975.04 3406.86,3966.71 2631.86,3966.71 2615.19,3950.04 2615.19,3883.37 2598.52,3866.71 2448.52,3866.71 2415.19,3833.37 2415.19,3683.37 2398.52,3666.71 2048.52,3666.71 2031.86,3650.04 2031.86,3326.86 2000,3295 v1(1964.34,3295) 1905,3295 1899.96,3300.04 1796.46,3300.04 ; v3@5106.94,4033.17 cw(c5088.9,4034.75) 5100.54,4020.88 cw(c5112.18,4007.01) v3@5113.76,4025.05
IN.L: R2.2 R5.2 R6.2 R7.2 R137.1 TP9.1 U26.5 | length 4045
  Top Layer w4: U26.5@-389.13,5000 -314.44,5000 -294.44,4980 v1(-265,4980) v1@-269.96,4975.04 ; TP9.1@76.12,3508.23 125,3557.11 125,4284.85 296.85,4456.7 296.85,4576.85 v1(320,4600) ; v1@315.15,4600 v1(320,4600) ; v1@317.57,4597.57 v1(320,4600)
  MidLayer1 w4: v1@240.19,5008.37 240,5008.56 v1(240,5015) 315,5015 385,4945 385,4625 360,4600 v1(320,4600) 317.76,4602.24 v1@317.76,4602.61
  MidLayer2 w4: v1(-250,3760) -275,3735 -330,3735 -350,3715 -350,3645 -373.44,3621.56 -416.63,3621.56 -442,3596.18 -442,3535 -415.23,3508.23 TP9.1@76.12,3508.23
  Bottom Layer w4: R5.2@-278.82,3740.45 R5.2@-278.82,3741.71 ; R2.2@-278.82,3795.91 R5.2@-278.82,3741.71 ; v1@-263.56,4975.04 -265,4976.48 v1(-265,4980) -134.96,4980 -130,4975.04 -52,4975.04 ; v1@-255.01,3751.93 cw(c-260.62,3742.91) -250,3742.91 ; v1(-250,3760) -250,3742.91 ; v1@-244.99,3751.93 ccw(c-239.38,3742.91) -250,3742.91 ; R7.2@-221.18,3685 R6.2@-221.18,3740.45 -247.81,3740.45 -248.81,3741.45 -248.81,3741.71 R5.2@-278.82,3741.71 ; R137.1@-160.85,5388.42 -98.42,5388.42 -64.81,5354.81 -64.81,4987.85 -52,4975.04 ; v1(240,5015) 167.97,5015 126.01,4973.04 90,4973.04 88,4975.04 -52,4975.04
IN.R: R10.2 R11.2 R12.2 R13.2 R15.2 R138.1 TP10.1 U26.6 | length 3088.1
  Top Layer w4: U26.6@-389.09,4950.04 U26.6@-389.13,4950 -335,4950 v1(-320,4935)
  MidLayer1 w4: v1(-368.14,4308.37) -395,4335.23 -395,4430 -327.12,4497.88 -327.12,4583.19 -403.48,4659.54 -403.48,4766.49 -297.14,4872.82 -297.14,4912.14 v1(-320,4935) -319.83,4935.17 v1@-319.17,4935.17
  MidLayer2 w4: v1(-355,4020) -420,3955 -420,3724.88 -475,3669.88 -475,3505.68 -377.56,3408.23 TP10.1@76.12,3408.23 ; v1(-320,4935) -320,4988.5 -295,5013.5 -236.5,5013.5 -210,5040 -210,5255 -197.96,5267.04 v1(-126.14,5267.04)
  Bottom Layer w4: v1(-368.14,4308.37) -368.14,4267.37 -340.31,4239.55 R15.2@-321.18,4239.55 R13.2@-321.18,4184.09 ; v1(-355,4020) -352.73,4017.73 R10.2@-321.18,4017.73 R11.2@-321.18,4073.18 ; R138.1@-160.85,5276.75 -135.85,5276.75 v1(-126.14,5267.04) ; R11.2@-321.18,4073.18 R12.2@-321.18,4128.64 ; R11.2@-321.18,4073.18 R12.2@-321.18,4128.64 ; R11.2@-321.18,4073.18 R12.2@-321.18,4128.64 ; R12.2@-321.18,4128.64 R13.2@-321.18,4184.09 ; R12.2@-321.18,4128.64 R13.2@-321.18,4184.09 ; R12.2@-321.18,4128.64 R13.2@-321.18,4184.09
ISP176X.BUS_DMA_ACK: U8.AF12 U61.116 | length 1616.7
  Top Layer w4: U8.AF12@5325.64,3692.57 cw(c5312.84,3679.77) 5330.94,3679.77 cw(c5349.05,3679.77) U8.AF12@5336.25,3692.57 ; U8.AF12@5325.75,3692.68 cw(c5313.22,3680.15) 5330.94,3680.15 cw(c5348.67,3680.15) U8.AF12@5336.14,3692.68 ; v1(5330.19,3541.71) 5331.52,3541.71 5356.86,3567.04 5356.86,3575.04 5323.52,3608.37 5323.52,3630 5330.95,3637.43 5330.94,3658.37 5330.94,3660 5330.94,3670 U8.AF12@5330.94,3697.87 ; v1@5330.19,3547.21 ccw(c5330.19,3563.71) 5341.86,3552.04 ; v1@5330.19,3551.21 ccw(c5330.19,3577.36) 5348.69,3558.87 ; v1(5332.86,2919.04) 5332.86,2904.02 5326.86,2898.02 5326.86,2588.37 5431.86,2483.37 5456.86,2483.37 5472.93,2499.45 5472.93,2522.93 5478.2,2528.2 U61.116@5516.83,2528.2 ; v1@5339.69,3541.71 cw(c5359.4,3541.71) 5345.46,3555.65 ; U61.116@5500.81,2525.37 ccw(c5493.98,2518.54) 5493.98,2528.2 ccw(c5493.98,2537.85) U61.116@5500.81,2531.02
  MidLayer1 w4: v1@5320.69,3541.71 cw(c5297.76,3541.71) 5313.97,3525.49 cw(c5330.19,3509.27) v1@5330.19,3532.21 ; v1@5324.69,3541.71 cw(c5311.41,3541.71) 5320.8,3532.32 cw(c5330.19,3522.93) v1@5330.19,3536.21 ; v1(5330.19,3541.71) 5306.86,3518.37 5306.86,3276.39 5346.86,3236.39 5346.86,3147.37 5331.86,3132.37 5331.86,2925.04 5332.86,2924.04 v1(5332.86,2919.04)
ISP176X.BUS_DMA_REQ: U8.AF17 U61.114 | length 1930.2
  Top Layer w4: v1@5473.52,2580.21 cw(c5473.52,2557.27) 5489.74,2573.49 cw(c5505.96,2589.71) v1@5483.02,2589.71 ; v1@5473.52,2584.21 cw(c5473.52,2570.93) 5482.91,2580.32 cw(c5492.3,2589.71) v1@5479.02,2589.71 ; v1(5473.52,2589.71) 5495.67,2567.57 ; 5483.2,2580.03 ccw(c5503.64,2600.47) U61.114@5503.64,2571.57 ; 5490.03,2573.2 ccw(c5503.64,2586.81) U61.114@5503.64,2567.57 ; 5496.86,2566.37 ccw(c5503.64,2573.16) U61.114@5503.64,2563.57 ; v1(5498.52,3434.37) 5498.52,3433.37 5520.02,3454.87 5520.02,3482.6 5534.61,3497.19 5542.38,3497.19 5552.81,3507.62 5552.81,3567 5543.17,3576.65 5543.17,3618.21 5527.8,3633.58 5527.8,3660 5527.8,3670 U8.AF17@5527.8,3697.87 ; v1@5498.52,3439.87 ccw(c5498.52,3455.57) 5509.62,3444.47 ; v1@5498.52,3443.87 ccw(c5498.52,3469.22) 5516.45,3451.3 ; U61.114@5500.43,2565.17 ccw(c5495.67,2561.62) 5495.67,2567.57 ; U61.114@5500.43,2569.96 cw(c5495.67,2573.51) 5495.67,2567.57 ; v1@5504.02,3434.37 cw(c5514.89,3434.37) 5507.21,3442.06 ; v1@5508.02,3434.37 cw(c5528.54,3434.37) 5514.03,3448.89 ; U61.114@5516.83,2567.57 5495.67,2567.57 ; U8.AF17@5522.49,3692.57 cw(c5509.69,3679.77) 5527.8,3679.77 cw(c5545.9,3679.77) U8.AF17@5533.1,3692.57 ; 5527.8,3680.15 cw(c5545.52,3680.15) 5532.99,3692.68 ccw(c5545.52,3680.15) 5527.8,3680.15 ; 5527.8,3680.15 ccw(c5510.07,3680.15) 5522.6,3692.68 cw(c5510.07,3680.15) 5527.8,3680.15
  MidLayer1 w4: 5454.71,2621.86 cw(c5422.56,2589.71) v1@5468.02,2589.71 ; v1@5459.47,3009.99 cw(c5443.26,2993.77) 5466.19,2993.77 cw(c5489.13,2993.77) v1@5472.91,3009.99 ; 5461.54,2615.03 cw(c5436.21,2589.71) v1@5472.02,2589.71 ; v1@5462.3,3012.82 cw(c5452.91,3003.43) 5466.19,3003.43 cw(c5479.47,3003.43) v1@5470.08,3012.82 ; v1(5466.19,3016.71) 5466.19,2970.6 5438.09,2942.5 5437.75,2942.5 5427.5,2932.25 5427.5,2917.75 5435,2910.25 5435,2885 5413.52,2863.52 5413.52,2823 5451.52,2785 5451.52,2625.04 5473.52,2603.04 v1(5473.52,2589.71) ; 5468.36,2608.2 cw(c5449.87,2589.71) v1@5476.02,2589.71 ; 5475.19,2601.37 cw(c5463.53,2589.71) v1@5480.02,2589.71
  MidLayer2 w4: v1@5456.69,3016.71 ccw(c5433.76,3016.71) 5449.97,3032.93 ccw(c5466.19,3049.14) v1@5466.19,3026.21 ; v1@5460.69,3016.71 ccw(c5447.41,3016.71) 5456.8,3026.1 ccw(c5466.19,3035.49) v1@5466.19,3022.21 ; v1(5466.19,3016.71) 5431.86,3051.04 5431.86,3162.04 5404.52,3189.37 5404.52,3230.06 5415.19,3240.73 5415.19,3317.52 5437,3339.33 5437,3368.9 5417.5,3388.4 5417.5,3447.25 5427.75,3457.5 5475.4,3457.5 v1(5498.52,3434.37) ; v1@5489.02,3434.37 ccw(c5466.09,3434.37) 5482.31,3450.59 ccw(c5498.52,3466.81) v1@5498.52,3443.87 ; v1@5493.02,3434.37 ccw(c5479.75,3434.37) 5489.14,3443.76 ccw(c5498.52,3453.15) v1@5498.52,3439.87
ISP176X.BUS_NCS: U8.AA12 U61.106 | length 2574.5
  Top Layer w4: v1@5059.47,2919.32 ccw(c5043.26,2903.11) 5043.26,2926.04 ccw(c5043.26,2948.98) v1@5059.47,2932.76 ; v1@5062.3,2922.15 ccw(c5052.91,2912.76) 5052.91,2926.04 ccw(c5052.91,2939.32) v1@5062.3,2929.93 ; v1@5072.52,2926.04 v1(5066.19,2926.04) 5031.09,2926.04 5022.52,2917.48 5022.52,2878.61 5056.13,2845 5153.56,2845 5165.19,2833.37 5165.19,2791.71 5173.52,2783.37 5198.86,2783.37 v1(5215.19,2767.04) ; v1@5205.69,2767.04 ccw(c5182.76,2767.04) 5198.97,2783.26 ccw(c5215.19,2799.48) v1@5215.19,2776.54 ; v1@5209.69,2767.04 ccw(c5196.41,2767.04) 5205.8,2776.43 ccw(c5215.19,2785.82) v1@5215.19,2772.54 ; v3(5311.26,3875.04) U8.AA12@5330.94,3894.72 ; U8.AA12@5323.44,3894.72 cw(c5305.34,3894.72) 5318.14,3881.92 cw(c5330.94,3869.12) U8.AA12@5330.94,3887.22 ; U8.AA12@5323.6,3894.72 cw(c5305.88,3894.72) 5318.41,3882.19 cw(c5330.94,3869.66) U8.AA12@5330.94,3887.38 ; U61.106@5523.52,2725.04 5546.19,2725.04 v1(5601.52,2669.71) ; U61.106@5532.85,2722.22 cw(c5539.67,2715.4) 5539.67,2725.04 cw(c5539.69,2734.71) U61.106@5532.85,2727.87 ; v1@5592.02,2669.71 ccw(c5569.09,2669.71) 5585.31,2685.93 ccw(c5601.52,2702.14) v1@5601.52,2679.21 ; v1@5596.02,2669.71 ccw(c5582.75,2669.71) 5592.14,2679.1 ccw(c5601.52,2688.49) v1@5601.52,2675.21 ; 5324.06,3887.84 ccw(c5336.87,3875.04) 5318.76,3875.04 cw(c5336.87,3875.04) 5324.06,3887.84 ; 5324.06,3887.84 cw(c5311.26,3900.65) 5311.26,3882.54 ccw(c5311.26,3900.65) 5324.06,3887.84
  MidLayer1 w4: v1(5066.19,2926.04) 5097.52,2957.37 5097.52,2979.9 5165.48,3047.86 5165.48,3064.6 ; v1@5066.19,2931.54 ccw(c5066.19,2944.82) 5075.58,2935.43 ccw(c5084.97,2926.04) v1@5071.69,2926.04 ; v1@5066.19,2935.54 ccw(c5066.19,2958.48) 5082.41,2942.26 ccw(c5098.63,2926.04) v1@5075.69,2926.04 ; 5165.04,3064.6 5165.04,3105 5165.04,3105.42 5184.67,3125.04 ; 5185,3125.37 5184.67,3125.04 ; 5287.4,3798.23 5287.4,3812.16 ; v3@5303.79,3874.39 cw(c5285.75,3872.81) 5299.62,3861.17 ; v3@5311.91,3867.57 ccw(c5313.49,3849.53) 5299.62,3861.17 ; 5184.67,3125.04 5277.52,3125.04 5290.19,3137.71 5290.19,3154.37 5239.86,3204.71 5239.86,3497.36 5259.21,3516.71 5270,3516.71 5281.86,3528.56 5281.86,3545 5287.4,3550.54 5287.4,3660 5287.4,3670 5287.4,3718.62 5287.4,3738.04 5287.4,3812.16 ; 5287.4,3812.16 5287.4,3831.66 cw(c5329.13,3831.66) 5299.62,3861.17
  Bottom Layer w4: v1@5210.21,2758.95 cw(c5204.73,2750.04) 5215.19,2750.04 ; v1(5215.19,2767.04) 5215.19,2750.04 ; v1@5220.17,2758.95 ccw(c5225.65,2750.04) 5215.19,2750.04 ; v1@5592.02,2669.71 cw(c5569.09,2669.71) 5585.31,2653.49 cw(c5601.52,2637.27) v1@5601.52,2660.21 ; v1@5596.02,2669.71 cw(c5582.75,2669.71) 5592.14,2660.32 cw(c5601.52,2650.93) v1@5601.52,2664.21 ; v1(5601.52,2669.71) 5548.52,2616.71 5348.52,2616.71 5215.19,2750.04
ISP176X.BUS_NIRQ: U8.AF15 U61.112 | length 1826.5
  Top Layer w4: U8.AF15@5443.75,3692.57 cw(c5430.95,3679.77) 5449.06,3679.77 cw(c5467.16,3679.77) U8.AF15@5454.36,3692.57 ; U8.AF15@5443.86,3692.68 cw(c5431.33,3680.15) 5449.06,3680.15 cw(c5466.78,3680.15) U8.AF15@5454.25,3692.68 ; U8.AF15@5449.06,3697.87 5449.06,3670 5449.06,3660 5449.06,3629.14 5453.19,3625 5453.19,3608.37 5420.86,3576.04 5415.7,3570.89 5415.7,3437.16 5410,3431.46 5410,3401.31 5436.31,3375 5436.31,3338.64 5423.02,3325.35 5423.02,3256.98 5438.91,3241.09 5489.08,3241.09 5538.96,3191.21 5611.02,3191.21 5618.86,3183.37 5618.86,3166.71 5628.19,3157.37 5640.19,3157.37 5648.52,3149.04 5648.52,3090.37 5665.19,3073.71 5665.19,3008.37 5623.52,2966.71 5590.19,2966.71 5548.52,2925.04 5495.15,2925.04 5482.38,2937.81 5466.92,2937.81 5462.23,2942.5 5404.15,2942.5 5375.88,2914.23 5354.38,2914.23 5334.86,2894.71 5334.86,2630.37 5348.52,2616.71 5490.19,2616.71 5498.52,2608.37 U61.112@5516.83,2608.37 ; 5492.03,2614.87 ccw(c5501.77,2624.61) U61.112@5503.22,2610.91 ; U61.112@5497.95,2608.95 ccw(c5502.9,2613.9) U61.112@5503.64,2606.94
ISP176X.ISP176X_NRESET: U8.AF9 U61.122 | length 2065.2
  Top Layer w4: v1@5065.19,3015.54 cw(c5065.19,2992.61) 5081.41,3008.82 cw(c5097.63,3025.04) v1@5074.69,3025.04 ; v1@5065.19,3019.54 cw(c5065.19,3006.26) 5074.58,3015.65 cw(c5083.97,3025.04) v1@5070.69,3025.04 ; v1(5065.19,3025.04) 5097.52,2992.71 5097.52,2934.37 5111.9,2920 5215,2920 5248.52,2886.48 5248.52,2491.71 5315.19,2425.04 5398.52,2425.04 5413.48,2410.09 U61.122@5516.83,2410.09 ; v1@5183.47,3473.43 ccw(c5167.26,3489.64) 5190.19,3489.64 ccw(c5213.13,3489.64) v1@5196.91,3473.43 ; v1@5186.3,3470.6 ccw(c5176.91,3479.99) 5190.19,3479.99 ccw(c5203.47,3479.99) v1@5194.08,3470.6 ; v1(5190.19,3466.71) 5190.19,3495.06 5206.02,3510.9 5206.02,3577.16 5201.02,3582.16 5201.02,3609.92 5212.83,3621.73 5212.83,3660 5212.83,3670 U8.AF9@5212.83,3697.87 ; U8.AF9@5207.53,3692.57 cw(c5194.73,3679.77) 5212.83,3679.77 cw(c5230.94,3679.77) U8.AF9@5218.14,3692.57 ; U8.AF9@5207.64,3692.68 cw(c5195.11,3680.15) 5212.83,3680.15 cw(c5230.56,3680.15) U8.AF9@5218.03,3692.68 ; U61.122@5500.81,2407.26 ccw(c5493.98,2400.43) 5493.98,2410.09 ccw(c5493.98,2419.74) U61.122@5500.81,2412.91
  MidLayer2 w4: v1(5065.19,3025.04) 5065.19,3033.37 5098.52,3066.71 5098.52,3133.37 5098.52,3171.33 5231.86,3304.67 5231.86,3425.04 v1(5190.19,3466.71) ; v1@5066.69,3025.04 cw(c5090.43,3025.04) 5073.64,3041.83 ; v1@5070.69,3025.04 cw(c5104.09,3025.04) 5080.47,3048.66 ; v1@5074.69,3025.04 cw(c5117.75,3025.04) 5087.3,3055.49 ; v1@5190.19,3457.21 cw(c5190.19,3434.27) 5206.41,3450.49 cw(c5222.63,3466.71) v1@5199.69,3466.71 ; v1@5190.19,3461.21 cw(c5190.19,3447.93) 5199.58,3457.32 cw(c5208.97,3466.71) v1@5195.69,3466.71
JTAG.DETECT: EXTHDR1.23 R233.2 | length 3135.4
  Top Layer w4: EXTHDR1.23@1779.21,3122.62 ccw(c1765.55,3136.28) 1784.87,3136.28 ccw(c1804.18,3136.28) EXTHDR1.23@1790.52,3122.62 ; EXTHDR1.23@1784.87,3071.85 1784.87,3274.87 1827.04,3317.04 2264.25,3317.04 2370,3211.29 2370,3170 2472,3068 2472,2447 2460,2435 2460,2221.31 2501.31,2180 2766.31,2180 2822.81,2236.5 2857.19,2236.5 2913.69,2180 3116.63,2180 3150,2180 3165.19,2195.19 3165.19,2322 3145,2342.19 v1(3145,2370) ; v1@3138.28,2363.28 cw(c3122.06,2347.06) 3145,2347.06 cw(c3167.93,2347.06) v1@3151.72,2363.28 ; v1@3141.11,2366.11 cw(c3131.72,2356.72) 3145,2356.72 cw(c3158.28,2356.72) v1@3148.89,2366.11
  Bottom Layer w4: R233.2@3097.23,2442.92 cw(c3083.79,2429.48) 3102.8,2429.48 ; 3102.8,2424.54 cw(c3128.78,2424.54) R233.2@3110.41,2442.92 ; 3102.8,2434.2 cw(c3119.12,2434.2) R233.2@3107.58,2445.75 ; R233.2@3103.82,2450 3102.8,2448.98 3102.8,2412.2 v1(3145,2370) ; v1@3135.5,2370 ccw(c3112.56,2370) 3128.78,2386.22 ccw(c3145,2402.43) v1@3145,2379.5 ; v1@3139.5,2370 ccw(c3126.22,2370) 3135.61,2379.39 ccw(c3145,2388.78) v1@3145,2375.5
JTAG.HARD.TCK: EXTHDR1.11 R223.2 | length 1849.4
  Top Layer w4: EXTHDR1.11@1973.84,3018.73 cw(c1973.84,3004.27) 1984.07,3014.49 ; EXTHDR1.11@1973.84,3071.85 1973.84,3024.72 v1(2006.86,2991.71) ; EXTHDR1.11@1977.84,3026.73 ccw(c1992.35,3026.73) 1982.09,3016.47 ; EXTHDR1.11@1981.84,3026.73 ccw(c2006.01,3026.73) 1988.92,3009.64 ; v1@1997.36,2991.71 ccw(c1974.42,2991.71) 1990.64,3007.93 ccw(c2006.86,3024.14) v1@2006.86,3001.21 ; v1@2001.36,2991.71 ccw(c1988.08,2991.71) 1997.47,3001.1 ccw(c2006.86,3010.49) v1@2006.86,2997.21
  MidLayer1 w4: v1@2000.14,2984.99 cw(c1983.92,2968.77) 2006.86,2968.77 cw(c2029.79,2968.77) v1@2013.57,2984.99 ; v1@2002.97,2987.82 cw(c1993.58,2978.43) 2006.86,2978.43 cw(c2020.14,2978.43) v1@2010.75,2987.82 ; v1(2006.86,2991.71) 2006.86,2831.67 2006.86,2817.32 2132.47,2691.71 2220,2691.71 2956.86,2691.71 v1(3106.86,2841.71) ; v1@3097.36,2841.71 cw(c3074.42,2841.71) 3090.64,2825.49 cw(c3106.86,2809.27) v1@3106.86,2832.21 ; v1@3101.36,2841.71 cw(c3088.08,2841.71) 3097.47,2832.32 cw(c3106.86,2822.93) v1@3106.86,2836.21
  Bottom Layer w4: R223.2@3097.23,2877.92 cw(c3081.32,2862.01) 3103.82,2862.01 cw(c3126.32,2862.01) R223.2@3110.41,2877.92 ; R223.2@3100.06,2880.75 cw(c3090.98,2871.67) 3103.82,2871.67 cw(c3116.66,2871.67) R223.2@3107.58,2880.75 ; v1@3100.14,2848.43 ccw(c3091.26,2857.31) 3103.82,2857.31 ; 3103.82,2862.32 ccw(c3127.47,2862.32) v1@3110.75,2845.6 ; 3103.82,2871.98 ccw(c3137.13,2871.98) v1@3113.57,2848.43 ; R223.2@3103.82,2885 3103.82,2844.75 v1(3106.86,2841.71)
JTAG.HARD.TDI: EXTHDR1.7 R220.2 | length 1474
  Top Layer w4: EXTHDR1.7@2031.18,3122.62 ccw(c2017.52,3136.28) 2036.83,3136.28 ccw(c2056.15,3136.28) EXTHDR1.7@2042.49,3122.62 ; v1@2033.47,3136.32 cw(c2025.36,3128.21) 2036.83,3128.21 ; EXTHDR1.7@2036.83,3071.85 2036.83,3139.68 v1(2040.19,3143.04) ; EXTHDR1.7@2036.83,3112 cw(c2071.23,3112) v1@2046.91,3136.32 ; EXTHDR1.7@2036.83,3121.66 cw(c2061.57,3121.66) v1@2044.08,3139.15 ; 2036.83,3131.32 cw(c2051.91,3131.32) v1@2041.25,3141.98
  Bottom Layer w4: v1(2040.19,3143.04) 2114.19,3217.04 2724.67,3217.04 2934,3007.71 3081.53,3007.71 R220.2@3103.82,3030 R220.2@3103.82,3028.82 ; v1@2040.19,3148.54 ccw(c2040.19,3161.82) 2049.58,3152.43 ccw(c2058.97,3143.04) v1@2045.69,3143.04 ; v1@2040.19,3152.54 ccw(c2040.19,3175.48) 2056.41,3159.26 ccw(c2072.63,3143.04) v1@2049.69,3143.04 ; 3087.07,3013.25 cw(c3103.82,2996.5) R220.2@3103.82,3020.19 ; 3088.26,3014.44 ccw(c3073.19,3029.51) R220.2@3094.5,3029.51 ; R220.2@3093.9,3020.08 cw(c3103.82,3010.16) R220.2@3103.82,3024.19 ; R220.2@3095.09,3021.27 ccw(c3086.85,3029.51) R220.2@3098.5,3029.51
JTAG.HARD.TDO: EXTHDR1.9 R221.2 | length 1432.4
  Top Layer w4: EXTHDR1.9@2005.34,3018.73 cw(c2005.34,3007.07) 2013.58,3015.31 ; EXTHDR1.9@2005.34,3071.85 2005.34,3023.56 v1(2040.19,2988.71) ; EXTHDR1.9@2009.34,3026.73 ccw(c2026.65,3026.73) 2014.41,3014.49 ; EXTHDR1.9@2013.34,3026.73 ccw(c2040.3,3026.73) 2021.24,3007.66 ; v1@2030.69,2988.71 ccw(c2007.76,2988.71) 2023.97,3004.93 ccw(c2040.19,3021.14) v1@2040.19,2998.21 ; v1@2034.69,2988.71 ccw(c2021.41,2988.71) 2030.8,2998.1 ccw(c2040.19,3007.49) v1@2040.19,2994.21
  Bottom Layer w4: v1(2040.19,2988.71) 2077.19,3025.71 2243.54,3025.71 2269.25,3000 2296.31,3000 2313.69,3017.37 2877.63,3017.37 2919.63,2975.37 3057.12,2975.37 3075,2957.5 R221.2@3103.82,2957.5 ; v1@2040.19,2994.21 ccw(c2040.19,3007.49) 2049.58,2998.1 ccw(c2058.97,2988.71) v1@2045.69,2988.71 ; v1@2040.19,2998.21 ccw(c2040.19,3021.14) 2056.41,3004.93 ccw(c2072.63,2988.71) v1@2049.69,2988.71 ; R221.2@3097.23,2950.91 ccw(c3081.32,2935) 3081.32,2957.5 ccw(c3081.32,2980) R221.2@3097.23,2964.09 ; R221.2@3100.06,2953.74 ccw(c3090.98,2944.66) 3090.98,2957.5 ccw(c3090.98,2970.34) R221.2@3100.06,2961.26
